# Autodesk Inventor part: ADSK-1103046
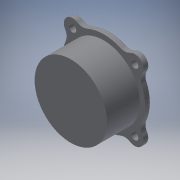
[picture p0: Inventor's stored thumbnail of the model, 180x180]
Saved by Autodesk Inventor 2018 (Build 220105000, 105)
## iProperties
Shininess: 50.0
Length Units: 11272
Angle Units: 11279
Time Units: 11290
Mass Units: 11286
Length Display Precision: 4
Angle Display Precision: 2
Compacted: True
Created: 2000-07
Part Number: ADSK-1103046
Document SubType Name: Modeling
Description: ENGINE COVER - REAR
Mass: 4.64243 g
Surface Area: 23.1415 cm^2
Volume: 1.71307 cm^3
Density: 2.71 g/cm^3
Material: Aluminum-6061
Appearance: Grey
Density: 0.0
Volumn: 0.0
Area: 0.0
PropertySet Name: Model Information
Control State: 0
Master: False
Checked Out: False
Author: Autodesk, Inc.
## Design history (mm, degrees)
node "Extrusion1" dims "d8" = 1.5875, "d9" = 0
  sketch "Sketch3"
    geometry: C1 r 2.54 at (-10.091, 9); C2 r 2.54 at (7.909, 9); C3 r 2.54 at (7.909, -9); C4 r 2.54 at (-10.091, -9); A1 r 1.048 centre (-10.091, 9) between (-10.08, 7.952) and (-9.043, 8.989); A2 r 1.048 centre (7.909, 9) between (7.898, 7.952) and (6.861, 8.989); A3 r 1.048 centre (-10.091, -9) between (-10.08, -7.952) and (-9.043, -8.989); A4 r 1.048 centre (7.909, -9) between (6.861, -8.989) and (7.898, -7.952); A5 r 12.002 centre (-1.091, 0) between (6.861, 8.989) and (-9.043, 8.989); A6 r 12.002 centre (-1.091, 0) between (7.898, -7.952) and (7.898, 7.952); A7 r 12.002 centre (-1.091, 0) between (-10.08, 7.952) and (-10.08, -7.952); A8 r 12.002 centre (-1.091, 0) between (-9.043, -8.989) and (6.861, -8.989)
    constraints: 16 point on circle, 12 centre point, 9 equal radius, 4 coincident, 2 horizontal alignment, 2 vertical alignment, 1 other
    dimensions: "d0" = 18 distance of A4.centre A3.centre; "d1" = 18 distance of A1.centre A3.centre; "d2" = 2.0955 diameter of A2; "d3" = 5.08 diameter of C2; "d4" = 9 horizontal distance of A1.centre A5.centre (= 0.5 x d1); "d5" = 9 horizontal distance of A3.centre A5.centre (= 0.5 x d0); "d7" = 12.0015 radius of A6
node "Fillet1" dims "d10" = 3.175
node "Extrusion2" dims "d12" = 9.525, "d13" = 0
  sketch "Sketch4"
    geometry: C1 r 10.477 at (-1.091, 0); A1 r 12.002 centre (-1.091, 0) between (-12.09, 4.802) and (-12.09, -4.802) reference
    constraints: 1 centre point, 1 coincident
    dimensions: "d11" = 20.955 diameter of C1
node "Extrusion3" dims "d15" = 9.525, "d16" = 0
  sketch "Sketch5"
    geometry: C1 r 8.89 at (1.091, 0); C2 r 10.477 at (1.091, 0) reference; A1 r 12.001 centre (1.091, 0) between (-9.908, 4.802) and (-9.908, -4.802) reference
    constraints: 1 centre point, 1 coincident
    dimensions: "d14" = 1.5875 radial gap between concentric circles of C2 C1
node "Fillet2" dims "d17" = 0.381
body "Solid1"
other parameters: "d6" = 24.003
